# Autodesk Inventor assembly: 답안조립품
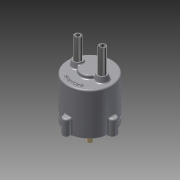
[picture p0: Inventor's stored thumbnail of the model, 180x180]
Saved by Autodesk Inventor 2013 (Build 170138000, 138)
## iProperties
Created: 2015-02
Part Number: 답안조립품
Document SubType Name: Assembly
Designer: WINDOWS7
Author: WINDOWS7
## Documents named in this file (13)
- C:\Users\WINDOWS7\Desktop\350208V1018\답안조립품.iam
- C:\Users\WINDOWS7\Desktop\350208V1018\몸체.ipt
- C:\Users\WINDOWS7\Desktop\350208V1018\커버.ipt
- C:\Users\WINDOWS7\Desktop\350208V1018\M5x0.5x20.ipt
- C:\Users\WINDOWS7\Desktop\350208V1018\오일실.ipt
- C:\Users\WINDOWS7\Desktop\350208V1018\베어링 NA 4900.ipt
- C:\Users\WINDOWS7\Desktop\350208V1018\메인 축.ipt
- C:\Users\WINDOWS7\Desktop\350208V1018\멈춤링 22 x 1.2.ipt
- C:\Users\WINDOWS7\Desktop\350208V1018\멈춤링 10 x 1.ipt
- C:\Users\WINDOWS7\Desktop\350208V1018\판캠.ipt
- C:\Users\WINDOWS7\Desktop\350208V1018\슬라이드 축.ipt
- C:\Users\WINDOWS7\Desktop\350208V1018\가변스프링1.ipt
- C:\Users\WINDOWS7\Desktop\350208V1018\가변스프링2.ipt
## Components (6 placed, 3 different names)
1. 가변스프링1:1
2. 가변스프링2:1
3. M5x0.5x20:1
4. M5x0.5x20:2
5. M5x0.5x20:3
6. M5x0.5x20:4
